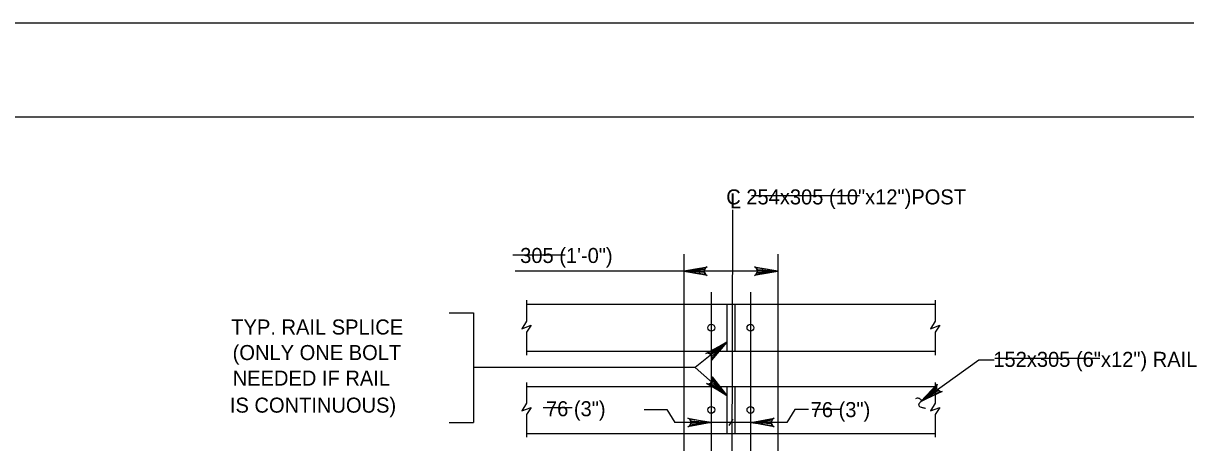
# Model space of a CAD drawing. Extents: x 179 to 454, y -271 to 54.
# Drawn here: x 371.83 to 381.12, y -3.35 to 0 of the extents above; entities that cross this region are included whole.
import ezdxf

# ---------------------------------------------------------------- set-up
doc = ezdxf.new("R2010")
doc.units = 0
for name, color, linetype in [('Level 1', 7, 'Continuous'), ('Level 2', 7, 'Continuous'), ('Level 3', 7, 'Continuous'), ('Level 41', 7, 'Continuous'), ('Level 63', 7, 'Continuous')]:
    doc.layers.add(name, color=color, linetype=linetype)

msp = doc.modelspace()

# ---------------------------------------------------------------- linework, layer by layer
at = {"layer": 'Level 1'}
msp.add_lwpolyline([(362.5132, -21.25), (394.0132, -21.25), (394.0132, -0.75), (362.5132, -0.75)], close=True, dxfattribs=at)
at = {"layer": 'Level 2'}
for p, q in [((375.8535, -2.2106), (375.8535, -2.3762)), ((379.1198, -2.2106), (379.1198, -2.3762)), ((375.8535, -2.2418), (379.1198, -2.2418)), ((377.1117, -2.2418), (377.1117, -2.6168)), ((377.4554, -2.2418), (377.4554, -2.6168)), ((377.5179, -2.2418), (377.5179, -2.6168)), ((377.8617, -2.2418), (377.8617, -2.6168)), ((375.8535, -2.3762), (375.8162, -2.4382)), ((375.8162, -2.4382), (375.8905, -2.4103)), ((375.8905, -2.4103), (375.8535, -2.466)), ((379.1198, -2.3762), (379.0825, -2.4382)), ((379.0825, -2.4382), (379.1567, -2.4103)), ((379.1567, -2.4103), (379.1198, -2.466)), ((375.8535, -2.466), (375.8535, -2.6481)), ((379.1198, -2.466), (379.1198, -2.6481)), ((375.8535, -2.6168), (379.1198, -2.6168)), ((377.1117, -2.6168), (377.1117, -2.8981)), ((377.8617, -2.6168), (377.8617, -2.8981)), ((375.8535, -2.8668), (375.8535, -3.0325)), ((379.1198, -2.8668), (379.1198, -3.0325)), ((375.8535, -2.8981), (379.1198, -2.8981)), ((377.1117, -2.8981), (377.1117, -3.2731)), ((377.4554, -2.8981), (377.4554, -3.2731)), ((377.5179, -2.8981), (377.5179, -3.2731)), ((377.8617, -2.8981), (377.8617, -3.2731)), ((375.8535, -3.0325), (375.8162, -3.0944)), ((379.1198, -3.0325), (379.0825, -3.0944)), ((375.8162, -3.0944), (375.8905, -3.0666)), ((375.8905, -3.0666), (375.8535, -3.1222)), ((375.8535, -3.1222), (375.8535, -3.3043)), ((379.0825, -3.0944), (379.1567, -3.0666)), ((379.1567, -3.0666), (379.1198, -3.1222)), ((379.1198, -3.1222), (379.1198, -3.3043)), ((375.8535, -3.2731), (379.1198, -3.2731)), ((377.1117, -3.2731), (377.1117, -3.6793)), ((377.8617, -3.2731), (377.8617, -3.6793))]:
    msp.add_line(p, q, dxfattribs=at)
for centre in [(377.3304, -2.4294), (377.6429, -2.4294), (377.3304, -3.0857), (377.6429, -3.0857)]:
    msp.add_circle(centre, 0.0273, dxfattribs=at)
at = {"layer": 'Level 3'}
for p, q in [((377.5001, -1.4887), (377.4867, -6.7043)), ((377.1117, -1.8425), (377.1117, -2.2418)), ((377.8617, -1.8425), (377.8617, -2.2418)), ((377.7362, -1.9779), (375.7643, -1.9779)), ((377.3304, -2.1467), (377.3304, -4.994)), ((377.6429, -2.1467), (377.6429, -4.994)), ((375.2355, -2.3108), (375.4291, -2.3108)), ((375.4291, -2.3108), (375.4291, -3.1853)), ((377.4554, -2.5457), (377.2016, -2.7481)), ((379.004, -3.0177), (379.4687, -2.6851)), ((379.4687, -2.6851), (379.5899, -2.6851)), ((377.2016, -2.7481), (375.4291, -2.7481)), ((377.4554, -2.9712), (377.2016, -2.7481)), ((376.795, -3.0837), (376.976, -3.0837)), ((376.976, -3.0837), (377.0397, -3.1855)), ((377.9973, -3.0837), (377.9336, -3.1855)), ((378.1074, -3.0837), (377.9973, -3.0837)), ((375.2355, -3.1853), (375.4291, -3.1853)), ((377.9336, -3.1855), (377.0397, -3.1855)), ((377.5026, -3.1597), (377.4707, -3.2113))]:
    msp.add_line(p, q, dxfattribs=at)
for points in [[(377.1117, -1.9779), (377.2981, -1.943), (377.2837, -1.9529), (377.2763, -1.9654), (377.2742, -1.9779), (377.2763, -1.9904), (377.2837, -2.0029), (377.2981, -2.0128), (377.1117, -1.9779), (377.2837, -2.0029), (377.2763, -1.9904), (377.1117, -1.9779), (377.2742, -1.9779), (377.2763, -1.9654), (377.1117, -1.9779), (377.2837, -1.9529)], [(377.8612, -1.9779), (377.6748, -2.0128), (377.6892, -2.0029), (377.6966, -1.9904), (377.6987, -1.9779), (377.6966, -1.9654), (377.6892, -1.9529), (377.6748, -1.943), (377.8612, -1.9779), (377.6892, -1.9529), (377.6966, -1.9654), (377.8612, -1.9779), (377.6987, -1.9779), (377.6966, -1.9904), (377.8612, -1.9779), (377.6892, -2.0029)], [(377.4554, -2.5457), (377.3314, -2.6892), (377.3365, -2.6725), (377.3345, -2.6582), (377.3283, -2.647), (377.3189, -2.6386), (377.3053, -2.6334), (377.2878, -2.6346), (377.4554, -2.5457), (377.3053, -2.6334), (377.3189, -2.6386), (377.4554, -2.5457), (377.3283, -2.647), (377.3345, -2.6582), (377.4554, -2.5457), (377.3365, -2.6725)], [(377.4554, -2.9712), (377.2923, -2.8743), (377.3097, -2.8763), (377.3235, -2.8718), (377.3333, -2.8639), (377.34, -2.8531), (377.3427, -2.8388), (377.3385, -2.8218), (377.4554, -2.9712), (377.3427, -2.8388), (377.34, -2.8531), (377.4554, -2.9712), (377.3333, -2.8639), (377.3235, -2.8718), (377.4554, -2.9712), (377.3097, -2.8763)], [(379.004, -3.0177), (379.1352, -2.8808), (379.1293, -2.8973), (379.1306, -2.9118), (379.1362, -2.9232), (379.1452, -2.9321), (379.1584, -2.9379), (379.1759, -2.9377), (379.004, -3.0177), (379.1584, -2.9379), (379.1452, -2.9321), (379.004, -3.0177), (379.1362, -2.9232), (379.1306, -2.9118), (379.004, -3.0177), (379.1293, -2.8973)], [(377.3304, -3.1855), (377.144, -3.2204), (377.1583, -3.2105), (377.1658, -3.198), (377.1679, -3.1855), (377.1658, -3.173), (377.1583, -3.1605), (377.144, -3.1506), (377.3304, -3.1855), (377.1583, -3.1605), (377.1658, -3.173), (377.3304, -3.1855), (377.1679, -3.1855), (377.1658, -3.198), (377.3304, -3.1855), (377.1583, -3.2105)], [(377.6474, -3.1855), (377.8338, -3.1506), (377.8195, -3.1605), (377.8121, -3.173), (377.8099, -3.1855), (377.8121, -3.198), (377.8195, -3.2105), (377.8338, -3.2204), (377.6474, -3.1855), (377.8195, -3.2105), (377.8121, -3.198), (377.6474, -3.1855), (377.8099, -3.1855), (377.8121, -3.173), (377.6474, -3.1855), (377.8195, -3.1605)]]:
    msp.add_lwpolyline(points, dxfattribs=at)
for points in [[(377.2367, -1.9988), (377.2367, -1.9571), (377.1117, -1.9779)], [(377.7362, -1.9571), (377.7362, -1.9988), (377.8612, -1.9779)], [(377.3429, -2.6088), (377.3688, -2.6414), (377.4537, -2.5473)], [(377.3784, -2.8769), (377.3521, -2.907), (377.4554, -2.9712)]]:
    msp.add_lwpolyline(points, close=True, dxfattribs=at)
for centre, radius, start, end in [((378.9816, -3.031), 0.0394, 101.24, 119.22297), ((378.9787, -3.0166), 0.0248, 78.5013, 101.24), ((378.972, -3.0496), 0.0585, 68.55376, 78.5013), ((378.9978, -3.0428), 0.0109, 141.43841, 177.1104), ((379.0046, -3.0431), 0.0178, 177.1104, 204.86978), ((379.0068, -3.0422), 0.0201, 204.86978, 233.05634), ((379.6998, -3.6024), 0.9087, 141.12339, 141.43841), ((381.9413, -5.4096), 3.788, 140.96911, 141.12339), ((378.9806, -3.0277), 0.0349, 55.672, 68.55376), ((379.0156, -3.0304), 0.0348, 233.05634, 254.40037), ((379.6187, -3.5267), 0.798, 140.21634, 140.9691), ((378.9798, -3.0289), 0.0364, 35.62317, 55.672), ((378.799, -2.8441), 0.2687, 320.21634, 321.51358), ((379.0802, -2.7991), 0.2749, 254.40037, 256.19123), ((379.0069, -3.0095), 0.00303, 321.51357, 35.62317), ((379.1129, -2.666), 0.412, 256.19123, 257.65415), ((379.0502, -2.9526), 0.1187, 257.65415, 260.92719), ((379.0723, -2.8139), 0.2591, 260.92719, 263.14214)]:
    msp.add_arc(centre, radius, start, end, dxfattribs=at)
at = {"layer": 'Level 41'}
for p, q in [((377.6505, -1.3753), (378.5155, -1.3753)), ((375.7447, -1.8487), (376.1637, -1.8487)), ((379.5968, -2.6738), (380.4349, -2.6738)), ((375.988, -3.066), (376.2177, -3.066)), ((378.1371, -3.0796), (378.3668, -3.0796))]:
    msp.add_line(p, q, dxfattribs=at)
at = {"layer": 'Level 63'}
msp.add_lwpolyline([(360.7633, -22), (394.7633, -22), (394.7633, 0), (360.7633, 0)], close=True, dxfattribs=at)

# ---------------------------------------------------------------- texts
at = {"layer": 'Level 3'}
for s, p in [('C 254x305 (10"x12")POST', (377.4497, -1.4457)), ('L', (377.4797, -1.4776)), ('305 (1\'-0")', (375.8032, -1.9131)), ('TYP. RAIL SPLICE', (373.4952, -2.484)), ('(ONLY ONE BOLT', (373.5062, -2.6879)), ('152x305 (6"x12") RAIL', (379.5836, -2.7422)), ('NEEDED IF RAIL', (373.5062, -2.8918)), ('IS CONTINUOUS)', (373.4841, -3.1077)), ('76 (3")', (376.0093, -3.1363)), ('76 (3")', (378.1242, -3.1433))]:
    msp.add_text(s, height=0.12, dxfattribs=at).set_placement(p)

doc.saveas('drawing.dxf')
